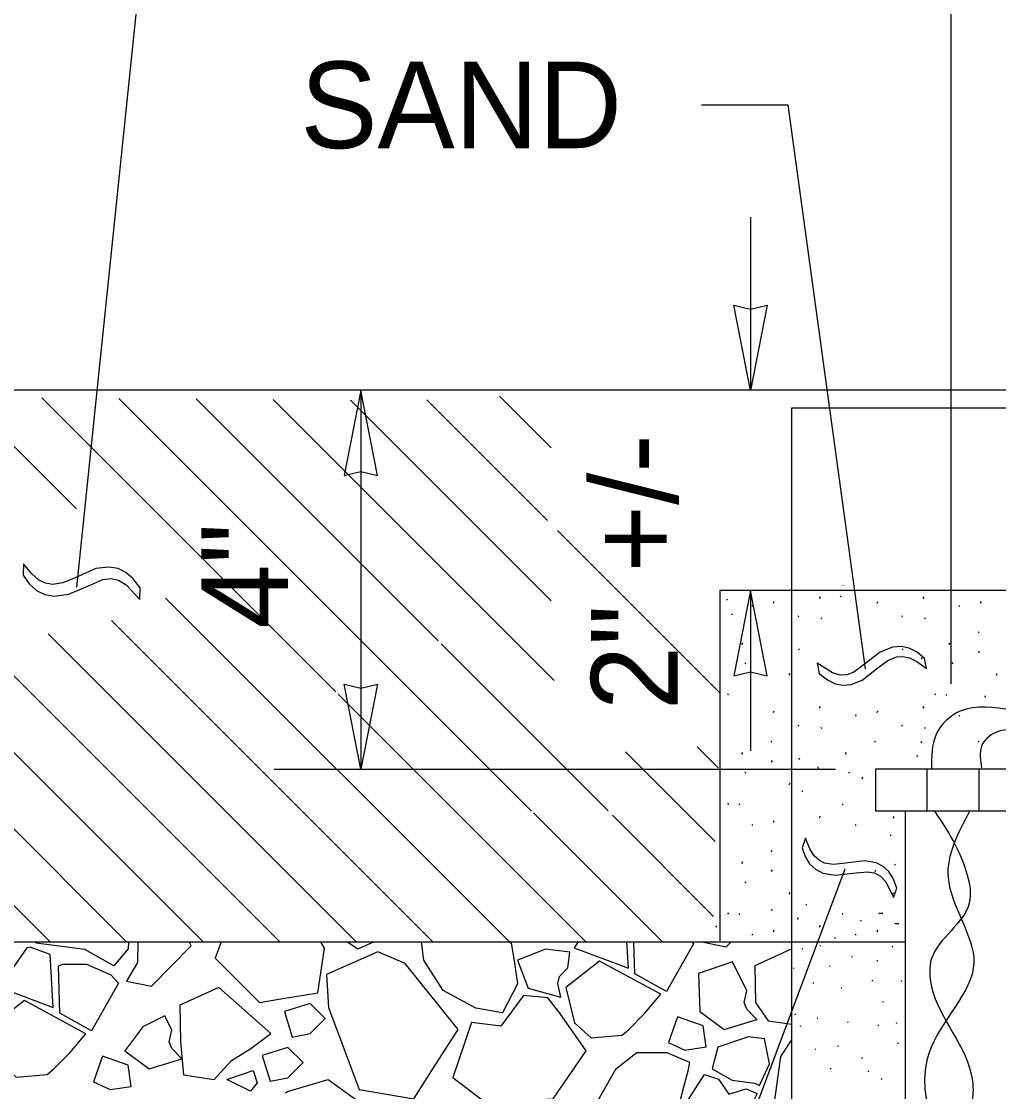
# Model space of a CAD drawing. Extents: x 99862 to 103151, y 100000 to 108153.
# Drawn here: x 102047.1 to 102227.7, y 100730.6 to 100928.3 of the extents above; entities that cross this region are included whole.
import ezdxf

# ---------------------------------------------------------------- set-up
doc = ezdxf.new("R2010")
doc.units = 0
for name, color, linetype in [('Level 1', 7, 'Continuous'), ('Level 10', 7, 'Continuous'), ('Level 12', 7, 'Continuous'), ('Level 14', 7, 'Continuous'), ('Level 15', 7, 'Continuous'), ('Level 18', 7, 'Continuous'), ('Level 20', 7, 'Continuous'), ('Level 34', 7, 'Continuous'), ('Level 60', 7, 'Continuous')]:
    doc.layers.add(name, color=color, linetype=linetype)

msp = doc.modelspace()

# ---------------------------------------------------------------- linework, layer by layer
at = {"layer": 'Level 1'}
for p, q in [((102176.16, 100823.2), (102176.16, 100758.48)), ((102214.42, 100790.15), (102214.42, 100782.45)), ((102224.01, 100790.15), (102224.01, 100782.45))]:
    msp.add_line(p, q, dxfattribs=at)
msp.add_lwpolyline([(102233.39, 100790.15), (102204.9, 100790.15), (102204.9, 100782.45), (102233.39, 100782.45)], close=True, dxfattribs=at)
at = {"layer": 'Level 10'}
for p, q in [((102191.69, 100860.19), (101997.64, 100860.19)), ((102387.58, 100860.19), (102188.15, 100860.19)), ((102210.43, 100782.45), (102210.43, 100476.2)), ((101997.64, 100758.27), (102175.03, 100758.27))]:
    msp.add_line(p, q, dxfattribs=at)
at = {"layer": 'Level 12'}
for points in [[(102262.86, 100816.95), (102258.99, 100818.48), (102252.97, 100818.02), (102239.06, 100800.83), (102220.59, 100800.91), (102216.16, 100796.64), (102215.26, 100790.24)], [(102263.74, 100814.42), (102257.8, 100809.98), (102245.55, 100808.67), (102238.74, 100808.01), (102233.4, 100798.24), (102227.16, 100796.97), (102224.53, 100794.42), (102224.53, 100790.4)], [(102215.84, 100782.45), (102221.83, 100770.84), (102222.26, 100765.43), (102215.28, 100755.18), (102215.28, 100749.99), (102222.79, 100732.97), (102222.79, 100728.93), (102217.14, 100716.2), (102215.56, 100703.64), (102221.65, 100686.22), (102222.81, 100678.94), (102217.47, 100653.33), (102215.88, 100635.58), (102223.94, 100609.75), (102223.94, 100603.4), (102213.55, 100570.79), (102213.55, 100564.45), (102222.62, 100531.63), (102222.05, 100522.64), (102215.57, 100506.44), (102216.29, 100495.34), (102220.82, 100479.43), (102220.33, 100468.35), (102213.26, 100454.4), (102211.15, 100448.92), (102208.41, 100428.39), (102196.89, 100414.83), (102187.15, 100409.34), (102178.2, 100399.1), (102167, 100388.13), (102158.35, 100386.88), (102131.31, 100384.82), (102107.2, 100377.93), (102097.84, 100373.13), (102091.49, 100372.84), (102056.43, 100377.89), (102044.53, 100373.13), (102029.23, 100367.65), (102018.2, 100365.77), (101986.09, 100371.4), (101976.55, 100369.78), (101955.56, 100362.42), (101950.08, 100362.2), (101925.86, 100365.31), (101890.08, 100353.94)], [(102222.34, 100782.45), (102218.33, 100770.19), (102223.09, 100754.41), (102214.77, 100737.67), (102214.77, 100727), (102224.29, 100705.35), (102224.29, 100693.23), (102214.87, 100673.81), (102215.95, 100662.7), (102223.24, 100637.54), (102224.54, 100628.51), (102216.75, 100605.57), (102216.87, 100594.46), (102223.94, 100571.23), (102223.8, 100561.07), (102221.7, 100550.68), (102214.71, 100532.22), (102216.73, 100525), (102220.82, 100504.46), (102221.49, 100497.68), (102216.13, 100475.03), (102217.3, 100466.91), (102218.37, 100455.26), (102216.06, 100447.76), (102208.41, 100437.52), (102201.58, 100427.09), (102194, 100406.26), (102188.74, 100400.61), (102161.97, 100393.83), (102149.56, 100385.1), (102130.79, 100378.47), (102120.92, 100378.4), (102087.72, 100378.8), (102077.64, 100376.16), (102060.47, 100370.24), (102051.38, 100370.39), (102026.13, 100375.29), (102020.5, 100375.37), (101996.48, 100368.51), (101976.34, 100365.23), (101948.49, 100366.75), (101942.67, 100364.37), (101927.72, 100359.42), (101891.02, 100362.52)]]:
    msp.add_spline(points, degree=3, dxfattribs=at)
at = {"layer": 'Level 14'}
for p, q in [((102191.44, 100757.02), (102191.33, 100756.85)), ((102194.77, 100757.56), (102194.63, 100757.56)), ((102208.11, 100757.3), (102208.02, 100757.49)), ((102200.68, 100755.39), (102200.59, 100755.58)), ((102205.31, 100754.87), (102205.19, 100754.69)), ((102189.9, 100753.35), (102189.76, 100753.35)), ((102196.56, 100753.87), (102196.45, 100753.7)), ((102193.51, 100750.58), (102193.42, 100750.77)), ((102204.42, 100750.99), (102204.33, 100751.18)), ((102209.81, 100750.86), (102209.72, 100751.05)), ((102198.71, 100749.81), (102198.57, 100749.81)), ((102206.39, 100747.12), (102206.25, 100747.12)), ((102190.15, 100744.73), (102190.06, 100744.92)), ((102191.09, 100742.76), (102190.98, 100742.58)), ((102194.3, 100744.09), (102194.16, 100744.09)), ((102199.88, 100743.29), (102199.79, 100743.48)), ((102205.53, 100742.77), (102205.44, 100742.96)), ((102208.88, 100743.11), (102208.79, 100743.29)), ((102193.89, 100738.36), (102193.8, 100738.54)), ((102198.06, 100739.09), (102197.94, 100738.91)), ((102209.1, 100739.62), (102208.99, 100739.45)), ((102202.5, 100736.72), (102202.41, 100736.91)), ((102196.72, 100734.82), (102196.58, 100734.82)), ((102203.64, 100734.43), (102203.52, 100734.25)), ((102189.49, 100733.45), (102189.47, 100733.45)), ((102206.07, 100733.05), (102205.96, 100732.87))]:
    msp.add_line(p, q, dxfattribs=at)
for points in [[(102066.91, 100758.27), (102066.85, 100757), (102064.23, 100753.84), (102058.83, 100756.89), (102049.84, 100758.05), (102049.78, 100758.27)], [(102068.64, 100758.27), (102068.61, 100754.47), (102066.54, 100751.02), (102071.15, 100750.1), (102078.52, 100757.54), (102078.13, 100758.27)], [(102084.06, 100758.27), (102082.91, 100755.28), (102091.12, 100747.07), (102095.06, 100747.73), (102101.9, 100748.87), (102103.11, 100757.09), (102102.43, 100758.27)], [(102136.94, 100758.27), (102137.65, 100758.09), (102138.22, 100754.31), (102138.8, 100750.53), (102136.01, 100745.19), (102131.08, 100746.01), (102125.08, 100749.3), (102121.47, 100754.88), (102121.08, 100758.27)], [(102150.01, 100758.27), (102149.25, 100757.18), (102159.27, 100753.41), (102158.98, 100758.27)], [(102170.97, 100758.27), (102171.3, 100757.9), (102166.3, 100749.13), (102160.49, 100752.37), (102160.31, 100758.27)], [(102189.47, 100756.97), (102182.66, 100753.82), (102182.73, 100747.09), (102185.1, 100743.71), (102189.47, 100743.08)], [(102054.82, 100754.18), (102059.18, 100754.15), (102063.69, 100752.21), (102065.07, 100750.64), (102060.08, 100741.86), (102054.27, 100745.1), (102054, 100753.85), (102054.82, 100754.18)], [(102100.48, 100741.32), (102103.27, 100744.12), (102100.48, 100746.91), (102095.72, 100745.43), (102097.19, 100740.67), (102097.19, 100740.67), (102100.48, 100741.32)], [(102169.73, 100738.27), (102173.64, 100738.85), (102173.06, 100742.75), (102168.36, 100744.4), (102166.71, 100739.7), (102166.71, 100739.7), (102169.73, 100738.27)], [(102096.39, 100733.17), (102099.18, 100735.96), (102096.39, 100738.75), (102091.63, 100737.27), (102093.11, 100732.51), (102093.11, 100732.51), (102096.39, 100733.17)], [(102189.47, 100724.82), (102186, 100726.84), (102187.46, 100737.09), (102189.47, 100740.17)], [(102063.51, 100731), (102067.42, 100731.58), (102066.84, 100735.49), (102062.14, 100737.14), (102060.48, 100732.43), (102060.48, 100732.43), (102063.51, 100731)], [(102170.65, 100735.96), (102166.46, 100737.75), (102160.83, 100737.8), (102156.89, 100734.68), (102153.11, 100728.11), (102150.48, 100719.24), (102152.37, 100711.77), (102158.77, 100707.5), (102163.13, 100709.39), (102165.75, 100714.64), (102164.11, 100721.87), (102167.89, 100725.48), (102170.37, 100734.72), (102170.65, 100735.96)], [(102085.09, 100732.85), (102089.94, 100734.52), (102090.67, 100732.21)], [(102090.67, 100732.21), (102089.49, 100730.69), (102085.09, 100732.85)], [(102095.92, 100730.4), (102096.27, 100730.61), (102103.82, 100732.85), (102114.89, 100724.84), (102116.87, 100718.56)]]:
    msp.add_lwpolyline(points, dxfattribs=at)
for points in [[(102048.12, 100757.14), (102043.03, 100749.92), (102053.04, 100746.14), (102052.47, 100755.91), (102048.77, 100757.31), (102048.77, 100757.31)], [(102118.05, 100754.3), (102112.96, 100756.43), (102103.52, 100752.25), (102103.85, 100746.17), (102109.51, 100730.98), (102119.61, 100729.25), (102123.72, 100735.66), (102127.82, 100742.06)], [(102146.56, 100751.89), (102148.12, 100753.45), (102148.45, 100756.4), (102143.94, 100756.9), (102138.76, 100754.92), (102140.74, 100749.74), (102146.8, 100748.03), (102146.27, 100750.61)], [(102159.33, 100742.07), (102162.28, 100745.03), (102165.26, 100748.58), (102153.93, 100754.7), (102147.71, 100749.83), (102149.31, 100743.3), (102152.39, 100740.55), (102158.14, 100741.05)], [(102180.69, 100747.06), (102181.16, 100749.21), (102178.49, 100754.57), (102172.22, 100752.43), (102172.49, 100745.39), (102176.96, 100742.1), (102182.99, 100743.94), (102181.14, 100745.83)], [(102085.98, 100736.34), (102089.53, 100738.55), (102093.24, 100741.33), (102083.6, 100749.87), (102076.44, 100746.55), (102076.51, 100739.83), (102077.06, 100733.69), (102082.77, 100732.86)], [(102135.71, 100742.72), (102130.29, 100743.38), (102126.84, 100733.19), (102132.83, 100728.68), (102145.4, 100729.25), (102151.47, 100738.13), (102146.63, 100745.1), (102144.41, 100747.91), (102139.9, 100748.39)], [(102053.11, 100734.81), (102056.06, 100737.76), (102059.04, 100741.31), (102047.71, 100747.43), (102041.49, 100742.57), (102043.09, 100736.04), (102046.17, 100733.29), (102051.91, 100733.78)], [(102074.47, 100739.79), (102074.94, 100741.95), (102073.61, 100744.61), (102069.55, 100742.59), (102066.27, 100738.12), (102070.74, 100734.83), (102076.77, 100736.68), (102074.92, 100738.56)], [(102182.63, 100732.18), (102183.48, 100731.73), (102185.34, 100735.75), (102184.43, 100740.36), (102181.48, 100740.72), (102175.81, 100738.83), (102174.75, 100734.8), (102178.44, 100732.75)], [(102181.03, 100731.15), (102183.06, 100730.26), (102179.8, 100723.76), (102176.92, 100723.1), (102172.65, 100725.32), (102170.44, 100729.26), (102173.35, 100733.74), (102175.9, 100732.92), (102177.83, 100730.16)]]:
    msp.add_lwpolyline(points, close=True, dxfattribs=at)
at = {"layer": 'Level 15'}
for p, q in [((102218.83, 100978.57), (102218.83, 100805.93)), ((102172.79, 100912.9), (102188.79, 100912.9)), ((102203.11, 100808.7), (102188.79, 100912.9)), ((102181.83, 100892.16), (102181.83, 100860.16)), ((102109.83, 100860.16), (102109.83, 100790.15)), ((102181.83, 100823.17), (102181.83, 100793.59)), ((102093.83, 100790.15), (102197.53, 100790.15)), ((102199.25, 100771.68), (102142.93, 100621.07))]:
    msp.add_line(p, q, dxfattribs=at)
msp.add_lwpolyline([(102070.96, 100955.28), (102057.3, 100823.8)], dxfattribs=at)
for points in [[(102181.83, 100860.16), (102178.75, 100875.88), (102181.83, 100875.15), (102184.91, 100875.88)], [(102109.83, 100860.16), (102106.75, 100844.43), (102109.83, 100845.16), (102112.91, 100844.43)], [(102181.83, 100823.17), (102178.75, 100807.45), (102181.83, 100808.18), (102184.91, 100807.45)], [(102109.83, 100790.18), (102106.75, 100805.9), (102109.83, 100805.17), (102112.91, 100805.9)]]:
    msp.add_lwpolyline(points, close=True, dxfattribs=at)
at = {"layer": 'Level 20'}
for p, q in [((102047.53, 100828.12), (102047.44, 100826.01)), ((102049.09, 100826.27), (102047.53, 100828.12)), ((102063.36, 100827.5), (102060.91, 100827.22)), ((102065, 100827.23), (102063.36, 100827.5)), ((102047.44, 100826.01), (102048.59, 100824.39)), ((102050.39, 100825.12), (102049.09, 100826.27)), ((102057.18, 100825.56), (102054.82, 100824.57)), ((102060.91, 100827.22), (102057.18, 100825.56)), ((102062.19, 100825.19), (102063.68, 100825.38)), ((102063.68, 100825.38), (102065.07, 100825.07)), ((102066.46, 100826.52), (102065, 100827.23)), ((102067.8, 100825.36), (102066.46, 100826.52)), ((102069.1, 100823.65), (102067.8, 100825.36)), ((102048.59, 100824.39), (102049.93, 100823.2)), ((102051.61, 100824.53), (102050.39, 100825.12)), ((102052.92, 100824.29), (102051.61, 100824.53)), ((102054.82, 100824.57), (102052.92, 100824.29)), ((102055.9, 100822.53), (102059.96, 100824.25)), ((102059.96, 100824.25), (102062.19, 100825.19)), ((102065.07, 100825.07), (102066.49, 100824.24)), ((102066.49, 100824.24), (102069.02, 100821.54)), ((102069.02, 100821.54), (102069.1, 100823.65)), ((102198.89, 100824.1), (102198.92, 100824.05)), ((102049.93, 100823.2), (102051.46, 100822.46)), ((102051.46, 100822.46), (102053.2, 100822.16)), ((102053.2, 100822.16), (102055.9, 100822.53)), ((102240.52, 100823.19), (102176.16, 100823.19)), ((102177.4, 100821.59), (102177.54, 100821.37)), ((102194.61, 100821.68), (102194.75, 100822)), ((102198.41, 100822.22), (102198.55, 100822)), ((102213.74, 100821.68), (102213.89, 100822)), ((102182.06, 100820.43), (102182.21, 100820.22)), ((102186.09, 100820.85), (102186.23, 100821.18)), ((102205.22, 100820.85), (102205.36, 100821.18)), ((102220.33, 100820.43), (102220.47, 100820.22)), ((102224.35, 100820.85), (102224.49, 100821.18)), ((102178.35, 100818.89), (102178.49, 100818.67)), ((102190.58, 100818.55), (102190.73, 100818.33)), ((102194.83, 100818.16), (102194.98, 100817.94)), ((102209.71, 100818.55), (102209.86, 100818.33)), ((102213.96, 100818.16), (102214.11, 100817.94)), ((102223.87, 100815.61), (102224.02, 100815.39)), ((102180.26, 100813.19), (102180.4, 100813.51)), ((102218.52, 100813.19), (102218.67, 100813.51)), ((102190.72, 100812.41), (102190.86, 100812.2)), ((102205.81, 100811.8), (102202.65, 100809.4)), ((102208.08, 100812.72), (102205.81, 100811.8)), ((102209.66, 100812.85), (102208.08, 100812.72)), ((102211.17, 100812.55), (102209.66, 100812.85)), ((102209.85, 100812.41), (102209.99, 100812.2)), ((102212.6, 100811.82), (102211.17, 100812.55)), ((102213.96, 100810.65), (102212.6, 100811.82)), ((102223.99, 100811.72), (102224.14, 100812.04)), ((102180.78, 100809.86), (102180.93, 100809.64)), ((102196.96, 100807.95), (102194.15, 100809.73)), ((102194.15, 100809.73), (102194.55, 100807.87)), ((102205.37, 100808.88), (102207.2, 100810.26)), ((102207.2, 100810.26), (102208.8, 100810.93)), ((102208.8, 100810.93), (102209.99, 100811.02)), ((102209.99, 100811.02), (102211.19, 100810.77)), ((102211.19, 100810.77), (102212.59, 100810.06)), ((102212.59, 100810.06), (102214.36, 100808.8)), ((102213.41, 100810.81), (102213.45, 100810.49)), ((102214.36, 100808.8), (102213.96, 100810.65)), ((102219.05, 100809.86), (102219.19, 100809.64)), ((102189, 100807.54), (102189.14, 100807.87)), ((102194.55, 100807.87), (102196.07, 100806.68)), ((102198.38, 100807.54), (102196.96, 100807.95)), ((102199.66, 100807.58), (102198.38, 100807.54)), ((102200.92, 100808.07), (102199.66, 100807.58)), ((102202.65, 100809.4), (102200.92, 100808.07)), ((102202.49, 100806.59), (102205.37, 100808.88)), ((102227.26, 100807.54), (102227.41, 100807.87)), ((102196.07, 100806.68), (102197.5, 100805.96)), ((102197.5, 100805.96), (102198.92, 100805.67)), ((102198.92, 100805.67), (102200.41, 100805.8)), ((102200.41, 100805.8), (102202.49, 100806.59)), ((102177.6, 100804.11), (102177.74, 100803.89)), ((102215.86, 100804.11), (102216.01, 100803.89)), ((102217.91, 100804.03), (102218.06, 100803.81)), ((102225.12, 100803.75), (102225.16, 100803.43)), ((102194.61, 100801.44), (102194.75, 100801.77)), ((102213.74, 100801.44), (102213.89, 100801.77)), ((102186.09, 100800.62), (102186.23, 100800.94)), ((102201.19, 100800.2), (102201.34, 100799.98)), ((102205.22, 100800.62), (102205.36, 100800.94)), ((102220.33, 100800.2), (102220.47, 100799.98)), ((102190.58, 100798.31), (102190.73, 100798.1)), ((102194.83, 100797.93), (102194.98, 100797.71)), ((102209.71, 100798.31), (102209.86, 100798.1)), ((102213.96, 100797.93), (102214.11, 100797.71)), ((102185.61, 100795.37), (102185.75, 100795.16)), ((102204.74, 100795.37), (102204.88, 100795.16)), ((102213.34, 100795.05), (102213.49, 100795.38)), ((102223.87, 100795.37), (102224.02, 100795.16)), ((102180.26, 100792.96), (102180.4, 100793.28)), ((102185.73, 100791.48), (102185.87, 100791.8)), ((102190.72, 100792.18), (102190.86, 100791.96)), ((102199.39, 100792.96), (102199.54, 100793.28)), ((102212.53, 100792.68), (102212.68, 100792.47)), ((102194.28, 100790.58), (102194.31, 100790.25)), ((102180.78, 100789.62), (102180.93, 100789.41)), ((102199.92, 100789.62), (102200.06, 100789.41)), ((102202.45, 100788.41), (102202.6, 100788.74)), ((102189, 100787.31), (102189.14, 100787.63)), ((102191.31, 100786.22), (102191.45, 100786)), ((102177.6, 100783.87), (102177.74, 100783.66)), ((102179.65, 100783.79), (102179.79, 100783.58)), ((102198.78, 100783.79), (102198.92, 100783.58)), ((102204.9, 100782.45), (102204.9, 100782.45)), ((102182.06, 100779.96), (102182.21, 100779.74)), ((102186.09, 100780.38), (102186.23, 100780.7)), ((102194.61, 100781.21), (102194.75, 100781.53)), ((102201.19, 100779.96), (102201.34, 100779.74)), ((102208.2, 100781.13), (102208.35, 100781.45)), ((102207.62, 100778.08), (102207.76, 100777.86)), ((102191.99, 100777.41), (102191.38, 100775.67)), ((102192.82, 100775.46), (102191.99, 100777.41)), ((102185.61, 100775.14), (102185.75, 100774.92)), ((102191.38, 100775.67), (102191.92, 100774.02)), ((102191.92, 100774.02), (102192.74, 100772.69)), ((102193.62, 100774.18), (102192.82, 100775.46)), ((102194.49, 100773.37), (102193.62, 100774.18)), ((102180.26, 100772.72), (102180.4, 100773.04)), ((102192.74, 100772.69), (102193.84, 100771.68)), ((102195.52, 100772.84), (102194.49, 100773.37)), ((102197.18, 100772.59), (102195.52, 100772.84)), ((102199.39, 100772.81), (102197.18, 100772.59)), ((102202.93, 100773.26), (102199.39, 100772.81)), ((102205.04, 100772.87), (102202.93, 100773.26)), ((102206.34, 100772.22), (102205.04, 100772.87)), ((102207.38, 100771.26), (102206.34, 100772.22)), ((102208.42, 100772.67), (102208.56, 100772.45)), ((102185.73, 100771.25), (102185.87, 100771.57)), ((102193.84, 100771.68), (102195.21, 100770.99)), ((102195.21, 100770.99), (102197.55, 100770.62)), ((102197.55, 100770.62), (102201.38, 100771.01)), ((102201.38, 100771.01), (102203.48, 100771.23)), ((102203.48, 100771.23), (102204.77, 100771.01)), ((102204.77, 100771.01), (102205.85, 100770.4)), ((102204.86, 100771.25), (102205, 100771.57)), ((102205.85, 100770.4), (102206.82, 100769.35)), ((102208.2, 100769.95), (102207.38, 100771.26)), ((102180.78, 100769.39), (102180.93, 100769.17)), ((102206.82, 100769.35), (102208.25, 100766.45)), ((102208.86, 100768.19), (102208.2, 100769.95)), ((102208.25, 100766.45), (102208.86, 100768.2)), ((102189, 100767.07), (102189.14, 100767.4)), ((102208.13, 100767.07), (102208.28, 100767.4)), ((102185.66, 100764.3), (102185.81, 100764.08)), ((102192.06, 100765.29), (102192.2, 100765.08)), ((102177.6, 100763.64), (102177.74, 100763.42)), ((102179.65, 100763.56), (102179.79, 100763.34)), ((102190.54, 100762.76), (102190.58, 100762.43)), ((102198.78, 100763.56), (102198.92, 100763.34)), ((102202.15, 100762.3), (102202.29, 100762.08)), ((102206.26, 100763.54), (102205.54, 100763.54)), ((102175.48, 100760.97), (102175.62, 100761.3)), ((102186.09, 100760.14), (102186.23, 100760.47)), ((102194.61, 100760.97), (102194.75, 100761.3)), ((102205.22, 100760.14), (102205.36, 100760.47)), ((102209.22, 100761.63), (102208.51, 100761.63)), ((102175.03, 100758.27), (102210.43, 100758.27)), ((102182.06, 100759.72), (102182.21, 100759.51)), ((102197.35, 100759.11), (102197.49, 100758.89)), ((102201.19, 100759.72), (102201.34, 100759.51))]:
    msp.add_line(p, q, dxfattribs=at)
msp.add_lwpolyline([(102210.42, 100769.74), (102210.49, 100769.77)], dxfattribs=at)
at = {"layer": 'Level 34'}
msp.add_lwpolyline([(102189.47, 100856.94), (102247.66, 100856.94), (102247.66, 100658.57), (102189.47, 100658.57)], close=True, dxfattribs=at)
at = {"layer": 'Level 60'}
for p, q in [((102144.99, 100849.56), (102135.47, 100859.08)), ((102057.29, 100838.27), (102036.68, 100858.88)), ((102105.22, 100804.48), (102050.93, 100858.77)), ((102141.4, 100782.44), (102065.17, 100858.67)), ((102124.11, 100813.87), (102079.42, 100858.57)), ((102145.58, 100806.54), (102093.66, 100858.46)), ((102125.84, 100840.43), (102107.91, 100858.36)), ((102144.32, 100836.09), (102122.03, 100858.38)), ((102094.86, 100758.27), (101997.64, 100855.49)), ((102080.72, 100758.27), (101997.64, 100841.35)), ((102144.99, 100821.27), (102125.84, 100840.43)), ((102176.08, 100804.33), (102146.16, 100834.25)), ((102066.58, 100758.27), (101997.64, 100827.21)), ((102137.29, 100758.27), (102073.78, 100821.78)), ((102123.14, 100758.27), (102063.77, 100817.65)), ((102109, 100758.27), (102052.1, 100815.17)), ((102052.43, 100758.27), (101997.64, 100813.07)), ((102155.52, 100782.46), (102124.67, 100813.31)), ((102151.43, 100758.27), (102105.69, 100804.02)), ((102175.85, 100790.42), (102171.96, 100794.31)), ((102175.31, 100776.82), (102158.76, 100793.37)), ((102165.57, 100758.27), (102141.76, 100782.08)), ((102175.02, 100762.96), (102156.33, 100781.65))]:
    msp.add_line(p, q, dxfattribs=at)
for points in [[(102107.36, 100758.27), (102109.3, 100756.98), (102112.28, 100758.27)], [(102172.82, 100758.27), (102177.37, 100757.36), (102178.27, 100758.27)]]:
    msp.add_lwpolyline(points, dxfattribs=at)

# ---------------------------------------------------------------- texts
at = {"layer": 'Level 18'}
msp.add_text('SAND', height=16, dxfattribs=at).set_placement((102098.66, 100904.9))
for s, p in [('2" +/-', (102168.38, 100801.07)), ('4"', (102096.38, 100816.16))]:
    msp.add_text(s, height=16, rotation=90, dxfattribs=at).set_placement(p)

doc.saveas('drawing.dxf')
